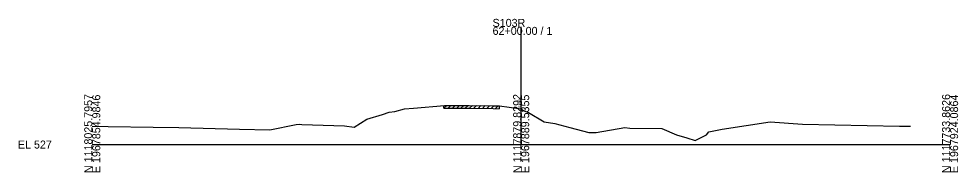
# Model space of a CAD drawing. Extents: x 974 to 1303, y 990 to 10019.
# Drawn here: x 974.3 to 1302.8, y 4490.3 to 4544 of the extents above; entities that cross this region are included whole.
import ezdxf

# ---------------------------------------------------------------- set-up
doc = ezdxf.new("R2010")
doc.units = 0
for name, color, linetype in [('Level 10', 7, 'Continuous'), ('Level 60', 7, 'Continuous'), ('Level 61', 7, 'Continuous'), ('Level 63', 7, 'Continuous')]:
    doc.layers.add(name, color=color, linetype=linetype)

msp = doc.modelspace()

# ---------------------------------------------------------------- linework, layer by layer
at = {"layer": 'Level 60'}
for p, q in [((1101.46, 4510.56), (1103.84, 4511.3)), ((1103.84, 4511.3), (1105.77, 4511.6)), ((1105.77, 4511.6), (1109.18, 4512.48)), ((1109.18, 4512.48), (1112.3, 4512.72)), ((1112.3, 4512.72), (1123.17, 4513.73)), ((1123.17, 4513.73), (1129.39, 4513.73)), ((1129.39, 4513.73), (1131.82, 4513.71)), ((1131.82, 4513.71), (1140.22, 4513.58)), ((1140.22, 4513.58), (1142.44, 4513.52)), ((1142.44, 4513.52), (1149.18, 4512.64)), ((1149.18, 4512.64), (1149.74, 4512.55)), ((1149.74, 4512.55), (1151.29, 4511.72)), ((1151.29, 4511.72), (1152.57, 4511.17)), ((1152.57, 4511.17), (1158.09, 4507.95)), ((1091.63, 4506.06), (1096.08, 4508.87)), ((1096.08, 4508.87), (1101.46, 4510.56)), ((1158.09, 4507.95), (1161.78, 4507.38)), ((1220.33, 4505.41), (1237.04, 4508)), ((1237.04, 4508), (1248.44, 4507.1)), ((1000, 4506.38), (1005.56, 4506.33)), ((1005.56, 4506.33), (1021.32, 4506.08)), ((1021.32, 4506.08), (1030.22, 4505.96)), ((1030.22, 4505.96), (1051.51, 4505.36)), ((1051.51, 4505.36), (1062.09, 4505.16)), ((1062.09, 4505.16), (1071.28, 4507.06)), ((1071.28, 4507.06), (1072.45, 4507.15)), ((1072.45, 4507.15), (1073.33, 4507.05)), ((1073.33, 4507.05), (1088.17, 4506.54)), ((1088.17, 4506.54), (1091.63, 4506.06)), ((1161.78, 4507.38), (1166.99, 4505.96)), ((1166.99, 4505.96), (1173.69, 4504.23)), ((1173.69, 4504.23), (1176.23, 4504.18)), ((1176.23, 4504.18), (1186.2, 4506)), ((1186.2, 4506), (1188.03, 4505.73)), ((1188.03, 4505.73), (1199.22, 4505.63)), ((1199.22, 4505.63), (1204.36, 4503.39)), ((1214.82, 4503.46), (1215.57, 4504.48)), ((1215.57, 4504.48), (1220.33, 4505.41)), ((1248.44, 4507.1), (1282.33, 4506.39)), ((1282.33, 4506.39), (1286.1, 4506.43)), ((1204.36, 4503.39), (1207.94, 4502.35)), ((1207.94, 4502.35), (1210.88, 4501.36)), ((1210.88, 4501.36), (1214.82, 4503.46))]:
    msp.add_line(p, q, dxfattribs=at)
at = {"layer": 'Level 61'}
for p, q in [((1122.95, 4512.71), (1123.97, 4513.73)), ((1122.95, 4512.71), (1122.95, 4513.71)), ((1122.95, 4512.71), (1123.17, 4512.73)), ((1123.17, 4512.73), (1129.39, 4512.73)), ((1124.45, 4512.73), (1125.45, 4513.73)), ((1125.95, 4512.73), (1126.95, 4513.73)), ((1127.45, 4512.73), (1128.45, 4513.73)), ((1128.95, 4512.73), (1129.94, 4513.73)), ((1129.39, 4512.73), (1131.82, 4512.71)), ((1130.45, 4512.72), (1131.44, 4513.72)), ((1131.82, 4512.71), (1140.22, 4512.58)), ((1131.95, 4512.71), (1132.93, 4513.69)), ((1133.45, 4512.69), (1134.43, 4513.67)), ((1134.95, 4512.66), (1135.93, 4513.65)), ((1136.45, 4512.64), (1137.43, 4513.62)), ((1137.95, 4512.62), (1138.93, 4513.6)), ((1139.45, 4512.59), (1140.43, 4513.57)), ((1140.22, 4512.58), (1142.26, 4512.53)), ((1140.95, 4512.56), (1141.92, 4513.54)), ((1142.26, 4513.53), (1142.26, 4512.53))]:
    msp.add_line(p, q, dxfattribs=at)
at = {"layer": 'Level 63'}
for p, q in [((1150, 4500), (1150, 4541.2)), ((1000, 4500), (1150, 4500)), ((1150, 4500), (1300, 4500))]:
    msp.add_line(p, q, dxfattribs=at)

# ---------------------------------------------------------------- texts
at = {"layer": 'Level 10'}
msp.add_text('539.41', height=0.9, rotation=90, dxfattribs=at).set_placement((1149.95, 4512.91))
at = {"layer": 'Level 63'}
for s, p in [('S103R', (1140, 4541.2)), ('62+00.00 / 1', (1140, 4538.4)), ('EL 527', (974, 4498.6))]:
    msp.add_text(s, height=2.8, dxfattribs=at).set_placement(p)
for s, p in [('N 1118025.7957', (1000, 4490)), ('N 1117879.8292', (1150, 4490)), ('E 1967889.5355', (1152.8, 4490)), ('N 1117733.8626', (1300, 4490)), ('E 1967924.0864', (1302.8, 4490)), ('E 1967854.9846', (1002.8, 4490))]:
    msp.add_text(s, height=2.8, rotation=90, dxfattribs=at).set_placement(p)

doc.saveas('drawing.dxf')
